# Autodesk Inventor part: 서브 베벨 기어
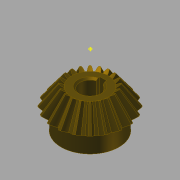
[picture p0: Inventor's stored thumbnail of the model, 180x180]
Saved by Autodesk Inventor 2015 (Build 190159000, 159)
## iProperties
Created: 2014-10
Part Number: 서브 베벨 기어
Material: 강철, 탄소
Document SubType Name: Modeling
Designer: KYOUNG IL JANG
Categories: <?xml version="1.0" encoding="UTF-16"?> <MemberInstance><Categories><FamilyTemplate><FamilyTemplateParameter ValueType="xs:double" Id="1" ObjectReferenceKey="da
Mass: 135.037 g
Surface Area: 63.6518 cm^2
Volume: 17.1585 cm^3
Density: 7.87 g/cm^3
Appearance: 얼룩무늬
CustomPartVersion: 1
Author: SeoGD™ [www.esajin.kr]
Revision Number: 1
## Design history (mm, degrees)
node "맨 위 점"
node "메쉬 평면2"
sketch "톱니 본체 스케치"
  geometry: L1 (0, 0)-(18.003, -31.331); L2 (18.003, -31.331)-(21.664, -28.891); L3 (21.664, -28.891)-(0, 0); L4 (20, -30)-(0, 0); L5 (10.813, -18.818)-(13.012, -17.352); L6 (18.003, -31.331)-(10.813, -18.818); L7 (21.664, -28.891)-(13.012, -17.352); L8 (0, -39.387)-(0, 6.564) reference; L9 (0, -30)-(21.664, -30)
  constraints: 16 end point, 4 point on line, 3 perpendicular, 2 collinear, 1 horizontal alignment, 1 vertical alignment
  dimensions: "d0" = 40 diameter of L4.start L8 (= da_de); "d1" = 36.00616 diameter of L1.end L8 (= da_dfe); "d2" = 43.3282 diameter of L2.end L8 (= da_dae); "d3" = 14.4 distance between parallel lines of L2 L5 (= da_b); "d4" = 28.8906 vertical distance of L2.end L1.start (= da_ve)
revolve "톱니 본체" sketch "톱니 본체 스케치" stored, may be unused: angle "d5" = 90 deg
node "시작점"
node "톱니 평면"
sketch "시작 스케치"
  geometry: L1 (0, -23.505)-(0, 10.645) reference; L2 (-0.834, -2.928)-(0.834, -2.928); A1 r 8.898 centre (-9.698, -3.713) between (-0.834, -2.928) and (-3.903, 3.04); A2 r 8.898 centre (9.698, -3.713) between (3.903, 3.04) and (0.834, -2.928); A3 r 27.357 centre (0, -24.037) between (3.903, 3.04) and (-3.903, 3.04); 1 further point
  constraints: 6 point on circle, 3 centre point, 3 symmetric about line, 2 end point, 1 coincident, 1 perpendicular, 1 other
  dimensions: "d7" = 8.89846 radius of A1 (= fd_rr); "d8" = 9.69794 horizontal distance of point (0, -24.037) A1.centre (= fd_x); "d9" = 20.32439 vertical distance of point (0, -24.037) A1.centre (= fd_y); "d57" = 27.35701 radius of A3 (= 0.5 x fd_dva + 0.3 x da_he); "d58" = 21.10901 distance from line of A3.centre L2 (= 0.5 x fd_dva - 1.12 x da_he)
node "끝점"
  node "끝 평면"
sketch "3D 스케치 오른쪽"
  node "Helical Curve Right" dims "d65" = 229.90621 (computed from da_dm, da_delta, da_beta), "d66" = 31.5, "d67" = 40 (= da_de), "d68" = -5.88003 (= -da_delta), "d69" = 12.16458 (computed from fd_loft, da_delta)
node "끝 평면 오른쪽"
sketch "끝 스케치 오른쪽"
  geometry: L1 (0, -22.649)-(0, 12.15) reference; L2 (-0.497, -1.72)-(0.497, -1.72); A1 r 5.299 centre (-5.775, -2.187) between (-0.497, -1.72) and (-2.324, 1.834); A2 r 5.299 centre (5.775, -2.187) between (2.324, 1.834) and (0.497, -1.72); A3 r 16.291 centre (0, -14.29) between (2.324, 1.834) and (-2.324, 1.834); 1 further point
  constraints: 6 point on circle, 3 centre point, 3 symmetric about line, 2 end point, 1 coincident, 1 perpendicular, 1 other
  dimensions: "d70" = 5.77526 horizontal distance of A3.centre A1.centre (computed from fd_x, fd_ratio); "d71" = 12.10346 vertical distance of point (0, -14.29) A1.centre (computed from fd_y, fd_ratio); "d72" = 5.29916 radius of A1 (computed from fd_rr, fd_ratio); "d73" = 12.57071 distance from line of point (0, -14.29) L2 (computed from d58, fd_ratio); "d74" = 16.29149 radius of A3 (computed from d57, fd_ratio)
feature "로프트 오른쪽" sketch "끝 스케치 오른쪽" dims "d75" = 0, "d77" = 0, "d79" = 0, "d80" = 90 deg, "d85" = 20, "d92" = 90 deg, "d93" = 90 deg, "da_teethtype" = 0 [user parameter]
sketch "3D 스케치 왼쪽"
  node "Helical Curve Left" dims "d26" = 229.90621 (computed from da_dm, da_delta, da_beta), "d27" = 12.16458 (computed from fd_loft, da_delta), "d28" = 40 (= da_de), "d29" = -5.88003 (= -da_delta)
node "끝 평면 왼쪽"
sketch "끝 스케치 왼쪽" dims "d56" = 10.82768 (derived)
  geometry: L1 (0, -35.087)-(0, 18.089) reference; L2 (-0.497, -1.716)-(0.497, -1.716); A1 r 5.299 centre (-5.775, -2.183) between (-0.497, -1.716) and (-2.324, 1.838); A2 r 5.299 centre (5.775, -2.183) between (2.324, 1.838) and (0.497, -1.716); A3 r 16.291 centre (0, -14.287) between (2.324, 1.838) and (-2.324, 1.838); 2 further points; 1 other entity
  constraints: 6 point on circle, 3 centre point, 3 symmetric about line, 2 end point, 1 coincident, 2 other
  dimensions: "d30" = 5.29916 radius of A1 (computed from fd_rr, fd_ratio); "d31" = 5.77526 horizontal distance of point (0, -14.287) A1.centre (computed from fd_x, fd_ratio); "d32" = 12.10346 vertical distance of A1.centre point (0, -14.287) (computed from fd_y, fd_ratio); "d61" = 16.29149 radius of A3 (computed from d57, fd_ratio); "d62" = 12.57071 distance from line of point (0, -14.287) L2 (computed from d58, fd_ratio)
feature "로프트 왼쪽" sketch "끝 스케치 왼쪽" dims "d35" = 0, "d37" = 0, "d39" = 0, "d40" = 90 deg, "d84" = 10, "d90" = 90 deg, "d91" = 90 deg, "da_teethtype" = 0 [user parameter]
sketch "본체 스케치"
  geometry: L1 (0, -35.038)-(0, -19.531) reference; L2 (18.003, -31.331)-(10.813, -18.818) reference; L3 (10.813, -18.818)-(0, -18.818); L4 (18.003, -31.331)-(0, -31.331)
  constraints: 4 end point, 2 perpendicular, 2 point on line
revolve "본체 고정" sketch "본체 스케치" stored, may be unused: angle "d46" = 90 deg
feature "피치 지름" dims angle "d47" = 90 deg
sketch "스케치8"
  geometry: C1 r 17 at (0, 0); 1 further point
  constraints: 1 centre point, 1 coincident
  dimensions: "d94" = 34 diameter of C1
extrude "돌출1" join sketch "스케치8" distance "d95" = 10; taper "d96" = 0 deg
sketch "스케치9"
  geometry: 1 further point
hole "구멍1" sketch "스케치9" at (0, 0) diameter "d97" = 12; stored, may be unused: countersink angle "d101" = 90 deg, drill point angle "d103" = 118 deg; dims "d98" = 6, "d99" = 4, "d100" = 2, "d102" = 8
sketch "스케치10"
  geometry: 1 further point
sketch "스케치11"
  geometry: 1 further point
sketch "스케치12"
  geometry: L1 (-2, 5.657)-(-2, 7.8); L2 (-2, 7.8)-(2, 7.8); L3 (2, 7.8)-(2, 5.657); A1 r 6 centre (0, 0) between (-2, 5.657) and (2, 5.657) reference; 1 further point
  constraints: 6 end point, 2 parallel, 2 point on circle, 1 perpendicular, 1 vertical
  dimensions: "d104" = 4 distance of L1.end L2.end; "d105" = 13.8 dimension on A1 L2
extrude "돌출2" cut sketch "스케치12" stored distance "d106" = 7; taper "d107" = 0 deg
chamfer "모따기1" distance "d108" = 1; stored, may be unused: second distance "d109" = 2, angle "d110" = 45 deg
body "Solid1"
feature "로프트" dims "d17" = 0, "d18" = 90 deg, "d19" = 0, "d20" = 90 deg, "d89" = 0, "da_teethtype" = 0 [user parameter]
pattern_circular "원형 패턴" dims angle "d22" = 360 deg, "d88" = 0, "da_teethtype" = 0 [user parameter]
pattern_circular "원형 패턴 오른쪽" dims angle "d82" = 360 deg, "da_teethtype" = 0 [user parameter]
pattern_circular "원형 패턴 왼쪽" dims angle "d42" = 360 deg, "da_teethtype" = 0 [user parameter]
sketch "끝 스케치"
  geometry: L1 (0, -15.359)-(0, 6.983) reference; L2 (-0.497, -1.72)-(0.497, -1.72); A1 r 5.299 centre (-5.775, -2.187) between (-0.497, -1.72) and (-2.324, 1.834); A2 r 5.299 centre (5.775, -2.187) between (2.324, 1.834) and (0.497, -1.72); A3 r 16.291 centre (0, -14.29) between (2.324, 1.834) and (-2.324, 1.834); 1 further point
  constraints: 6 point on circle, 3 centre point, 3 symmetric about line, 2 end point, 1 coincident, 1 other
  dimensions: "d12" = 5.29916 radius of A1 (computed from fd_rr, fd_ratio); "d15" = 5.77526 horizontal distance of A1.centre point (0, -14.29) (computed from fd_x, fd_ratio); "d16" = 12.10346 vertical distance of A1.centre point (0, -14.29) (computed from fd_y, fd_ratio); "d59" = 16.29149 radius of A3 (computed from d57, fd_ratio); "d60" = 12.57071 distance from line of A3.centre L2 (computed from d58, fd_ratio)
sketch "Sketch6"
  geometry: L1 (20, -30)-(0, 0) reference; L2 (0, -37.8)-(0, 6.3) reference
body "Srf1"
other parameters: "da_b" = 14.4 [user parameter; used in 2 equation terms], "da_de" = 40 [user parameter; used in 4 equation terms], "da_dae" = 43.3282 [user parameter; used in 2 equation terms], "da_dfe" = 36.00616 [user parameter; used in 1 equation term], "da_le" = 36.05551 [user parameter; used in 1 equation term], "da_omega" = 90 deg [user parameter; used in 1 equation term], "da_beta" = 0 [user parameter; used in 2 equation terms], "da_delta" = 5.88003 [user parameter; used in 8 equation terms], "da_alpha" = 20 deg [user parameter; used in 2 equation terms], "da_he" = 4.4 [user parameter; used in 4 equation terms], "da_ve" = 28.8906 [user parameter; used in 1 equation term], "fd_dv" = 48.07402 (computed from da_de, da_delta) [user parameter; used in 1 equation term], "fd_dva" = 52.07402 (computed from da_dae, da_delta) [user parameter; used in 3 equation terms], "fd_dvb" = 45.1748 (computed from fd_dv, da_alpha) [user parameter; used in 2 equation terms], "da_zv" = 240.37008 [user parameter; used in 1 equation term], "fd_loft" = 14.62 (= da_b + 0.05 x da_he) [user parameter; used in 4 equation terms], "fd_ratio" = 5.95514 (computed from da_le, fd_loft) [user parameter; used in 15 equation terms], "fd_rr" = 8.89846 (computed from fd_dd, fd_dvb) [user parameter; used in 6 equation terms], "fd_angle" = 0.66075 (computed from da_zv) [user parameter; used in 4 equation terms], "fd_x1" = 1.58709 (computed from da_dvw, fd_angle) [user parameter; used in 1 equation term], "fd_y1" = 23.98456 (computed from da_dvw, fd_angle) [user parameter; used in 1 equation term], "fd_x2" = 8.11084 (computed from fd_rr, fd_angle2, fd_angle) [user parameter; used in 1 equation term], "fd_y2" = 3.66016 (computed from fd_rr, fd_angle2, fd_angle) [user parameter; used in 1 equation term], "fd_x" = 9.69794 (= fd_x1 + fd_x2) [user parameter; used in 4 equation terms], "fd_y" = 20.32439 (= fd_y1 - fd_y2) [user parameter; used in 4 equation terms], "fd_angle2" = 3.57832 (computed from fd_dvb, fd_dd, da_alpha) [user parameter; used in 2 equation terms], "fd_dd" = 48.55402 (= fd_dva - 0.8 x da_he) [user parameter; used in 2 equation terms], "da_dvw" = 48.07402 [user parameter; used in 2 equation terms], "d11" = 14.62 (= fd_loft), "da_dm" = 32.01232 [user parameter; used in 2 equation terms], "da_x" = 0 [user parameter], "da_m" = 2 [user parameter], "d48" = 0, "d49" = 0, "d50" = 90 deg (= da_omega), "d51" = 9 deg (computed from da_z), "d52" = 0, "d53" = 0, "d54" = 0
